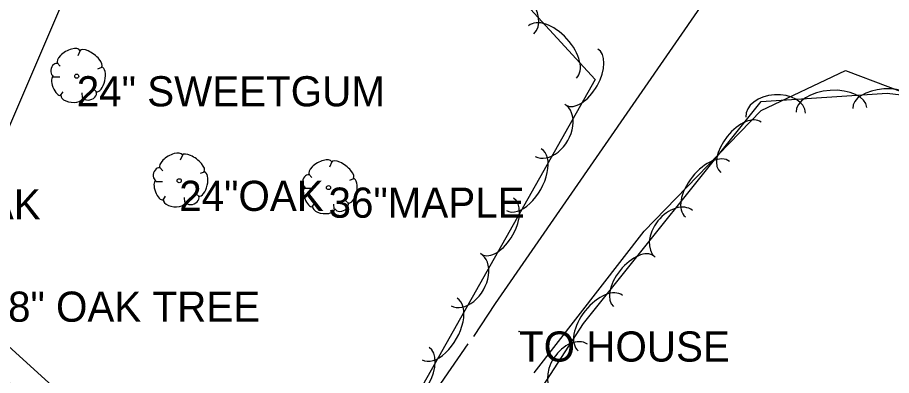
# Model space of a CAD drawing. Extents: x 1441650 to 1491889, y 345904 to 358319.
# Drawn here: x 1444464.6 to 1444609.3, y 355575.8 to 355635.2 of the extents above; entities that cross this region are included whole.
import ezdxf

# ---------------------------------------------------------------- set-up
doc = ezdxf.new("R2010")
doc.units = 0
for name, color, linetype in [('S_FENCE', 7, 'Continuous'), ('S_GRAVEL_ROAD', 7, 'Continuous'), ('S_MSC_PT_SYM', 7, 'Continuous'), ('S_PARKING', 7, 'Continuous'), ('S_SANITARY_SEWER', 7, 'Continuous'), ('S_SURVEY_TEXT_ANNOT', 7, 'Continuous'), ('S_TREE', 7, 'Continuous'), ('S_TREE_ANNOT', 7, 'Continuous')]:
    doc.layers.add(name, color=color, linetype=linetype)

msp = doc.modelspace()

# ---------------------------------------------------------------- linework, layer by layer
at = {"layer": 'S_FENCE'}
msp.add_line((1444477.43, 355650.46), (1444449.11, 355584.29), dxfattribs=at)
at = {"layer": 'S_GRAVEL_ROAD'}
msp.add_lwpolyline([(1444464.93, 355515.96), (1444478.42, 355517.94), (1444493.17, 355523.48), (1444501.71, 355529.9), (1444509.76, 355538.54), (1444517.12, 355549.17), (1444524.47, 355559.8), (1444531.83, 355570.43), (1444539.19, 355581.05)], dxfattribs=at)
at = {"layer": 'S_MSC_PT_SYM'}
msp.add_lwpolyline([(1444547.62, 355583.13), (1444547.62, 355583.18), (1444547.62, 355583.13), (1444547.57, 355583.13), (1444547.62, 355583.13), (1444547.62, 355583.08), (1444547.62, 355583.13), (1444547.67, 355583.13)], dxfattribs=at)
at = {"layer": 'S_PARKING'}
for points in [[(1444578.62, 355638.4), (1444543.68, 355587.74), (1444540.09, 355582.28)], [(1444550.14, 355576.27), (1444568.37, 355599.77), (1444587.73, 355619.76), (1444601.67, 355626.4), (1444615.72, 355621.1), (1444629.66, 355608.96), (1444629.45, 355607.81)]]:
    msp.add_lwpolyline(points, dxfattribs=at)
at = {"layer": 'S_SANITARY_SEWER'}
msp.add_line((1444417.64, 355621.87), (1444509.16, 355538.88), dxfattribs=at)
at = {"layer": 'S_TREE'}
for p, q in [((1444474.93, 355629.7), (1444474.54, 355628.85)), ((1444471.13, 355627.69), (1444471.63, 355627.1)), ((1444478.49, 355626.91), (1444477.83, 355626.64)), ((1444470.47, 355625.36), (1444471.59, 355625.36)), ((1444471.63, 355622.18), (1444472.1, 355622.88)), ((1444477.72, 355622.8), (1444477.25, 355623.23)), ((1444475.31, 355621.91), (1444475.24, 355622.69)), ((1444491.9, 355612.36), (1444491.51, 355611.51)), ((1444488.1, 355610.35), (1444488.6, 355609.77)), ((1444516.63, 355611.24), (1444516.24, 355610.39)), ((1444495.46, 355609.57), (1444494.8, 355609.3)), ((1444512.83, 355609.22), (1444513.33, 355608.64)), ((1444520.19, 355608.45), (1444519.53, 355608.18)), ((1444487.44, 355608.02), (1444488.57, 355608.02)), ((1444488.6, 355604.85), (1444489.07, 355605.54)), ((1444494.69, 355605.47), (1444494.22, 355605.89)), ((1444512.17, 355606.9), (1444513.3, 355606.9)), ((1444492.29, 355604.58), (1444492.21, 355605.35)), ((1444513.33, 355603.72), (1444513.8, 355604.42)), ((1444517.02, 355603.45), (1444516.94, 355604.22)), ((1444519.42, 355604.34), (1444518.95, 355604.77))]:
    msp.add_line(p, q, dxfattribs=at)
for points in [[(1444557.01, 355725.91), (1444533.9, 355718.62), (1444518.05, 355707.28), (1444510.99, 355685.16), (1444493.44, 355661.38), (1444490.77, 355641.91), (1444506.42, 355640.53), (1444528.88, 355643.64), (1444546.39, 355640.04), (1444560.23, 355624.89), (1444529.91, 355571.12), (1444517.35, 355554.35), (1444502.79, 355544.64), (1444481.93, 355553.25), (1444445.1, 355595.23)], [(1444643.85, 355606.23), (1444628.8, 355565.78), (1444601.88, 355520.54), (1444585.03, 355496.34), (1444569.38, 355495.99), (1444553.26, 355513.36), (1444546.13, 355565.67), (1444558.31, 355584.45), (1444587.71, 355621.24), (1444608.59, 355622.62), (1444628.66, 355620.28), (1444641.87, 355608.62)]]:
    msp.add_lwpolyline(points, dxfattribs=at)
for centre in [(1444474.37, 355625.46), (1444491.34, 355608.12), (1444516.07, 355606.99)]:
    msp.add_circle(centre, 0.341, dxfattribs=at)
for centre, major_axis, ratio, start_param, end_param in [((1444546.73, 355636.14), (-3.34, 3.66), 0.685267, 3.141593, 6.283185), ((1444553.17, 355629.48), (-3.96, 4.33), 0.550045, 3.141593, 6.283185), ((1444473.03, 355628.66), (1.86, 1.08), 0.471018, 0, 3.141593), ((1444476.69, 355628.33), (-1.81, 1.36), 0.405113, 3.141593, 6.283186), ((1444558.04, 355625.31), (2.63, 4.66), 0.540691, 3.141528, 6.28312), ((1444470.8, 355626.54), (0.31, 1.03), 0.646762, 0, 3.141593), ((1444478.04, 355624.93), (0.46, 2.04), 0.482994, 3.141593, 6.283185), ((1444471.1, 355623.89), (-0.61, 1.6), 0.420543, 6.283185, 9.424777), ((1444476.52, 355622.4), (1.09, 0.46), 0.711534, 3.141592, 6.283185), ((1444599.37, 355619.88), (-5.86, -0.39), 0.55008, 3.141593, 6.283185), ((1444608.22, 355620.47), (-5.33, -0.35), 0.540699, 3.141593, 6.283185), ((1444473.56, 355622.11), (-1.83, 0.19), 0.529943, 0, 3.141593), ((1444590.15, 355619.01), (-4.94, -0.33), 0.685311, 3.141593, 6.283185), ((1444552.75, 355616.47), (2.43, 4.32), 0.6853, 3.141482, 6.283075), ((1444584.36, 355613.66), (-3.34, -4.18), 0.540699, 3.141593, 6.283185), ((1444490, 355611.32), (1.86, 1.08), 0.471018, 0, 3.141593), ((1444493.66, 355611), (-1.81, 1.36), 0.405113, 3.141593, 6.283186), ((1444548.43, 355608.28), (2.88, 5.11), 0.550071, 3.141525, 6.283118), ((1444514.73, 355610.2), (1.86, 1.08), 0.471018, 0, 3.141593), ((1444518.39, 355609.87), (-1.81, 1.36), 0.405113, 3.141593, 6.283186), ((1444578.83, 355606.73), (-3.66, -4.59), 0.55008, 3.141593, 6.283185), ((1444487.77, 355609.21), (0.31, 1.03), 0.646762, 0, 3.141593), ((1444495.01, 355607.59), (0.46, 2.04), 0.482994, 3.141593, 6.283185), ((1444512.5, 355608.08), (0.31, 1.03), 0.646762, 0, 3.141593), ((1444519.74, 355606.46), (0.46, 2.04), 0.482994, 3.141593, 6.283185), ((1444488.07, 355606.56), (-0.61, 1.6), 0.420543, 6.283185, 9.424777), ((1444512.8, 355605.43), (-0.61, 1.6), 0.420543, 6.283185, 9.424777), ((1444493.49, 355605.07), (1.09, 0.46), 0.711534, 3.141592, 6.283185), ((1444490.54, 355604.78), (-1.83, 0.19), 0.529943, 0, 3.141593), ((1444518.22, 355603.94), (1.09, 0.46), 0.711534, 3.141592, 6.283185), ((1444544.07, 355600.55), (2.63, 4.66), 0.540691, 3.141528, 6.28312), ((1444573.26, 355599.33), (-3.09, -3.87), 0.685311, 3.141593, 6.283185), ((1444515.27, 355603.65), (-1.83, 0.19), 0.529943, 0, 3.141593), ((1444538.79, 355591.71), (2.43, 4.32), 0.6853, 3.141482, 6.283075), ((1444566.62, 355591.45), (-3.34, -4.18), 0.540699, 3.141593, 6.283185), ((1444561.09, 355584.52), (-3.66, -4.59), 0.55008, 3.141593, 6.283185), ((1444534.47, 355583.52), (2.88, 5.11), 0.550071, 3.141525, 6.283118), ((1444463.68, 355577.66), (3.27, -3.73), 0.685309, 3.141757, 6.28335), ((1444556.25, 355576.88), (-2.7, -4.16), 0.685311, 3.141593, 6.283185), ((1444530.11, 355575.79), (2.63, 4.66), 0.540691, 3.141528, 6.28312)]:
    msp.add_ellipse(centre, major_axis=major_axis, ratio=ratio, start_param=start_param, end_param=end_param, dxfattribs=at)

# ---------------------------------------------------------------- texts
at = {"layer": 'S_SURVEY_TEXT_ANNOT'}
msp.add_text('TO HOUSE', height=5, dxfattribs=at).set_placement((1444547.62, 355578.13))
at = {"layer": 'S_TREE_ANNOT'}
for s, p in [('24" SWEETGUM', (1444474.37, 355620.46)), ('24"OAK', (1444491.34, 355603.12)), ('36"MAPLE', (1444516.07, 355601.99)), ('48" OAK', (1444442.62, 355601.7)), ('18" OAK TREE', (1444459.27, 355584.74))]:
    msp.add_text(s, height=5, dxfattribs=at).set_placement(p)

doc.saveas('drawing.dxf')
